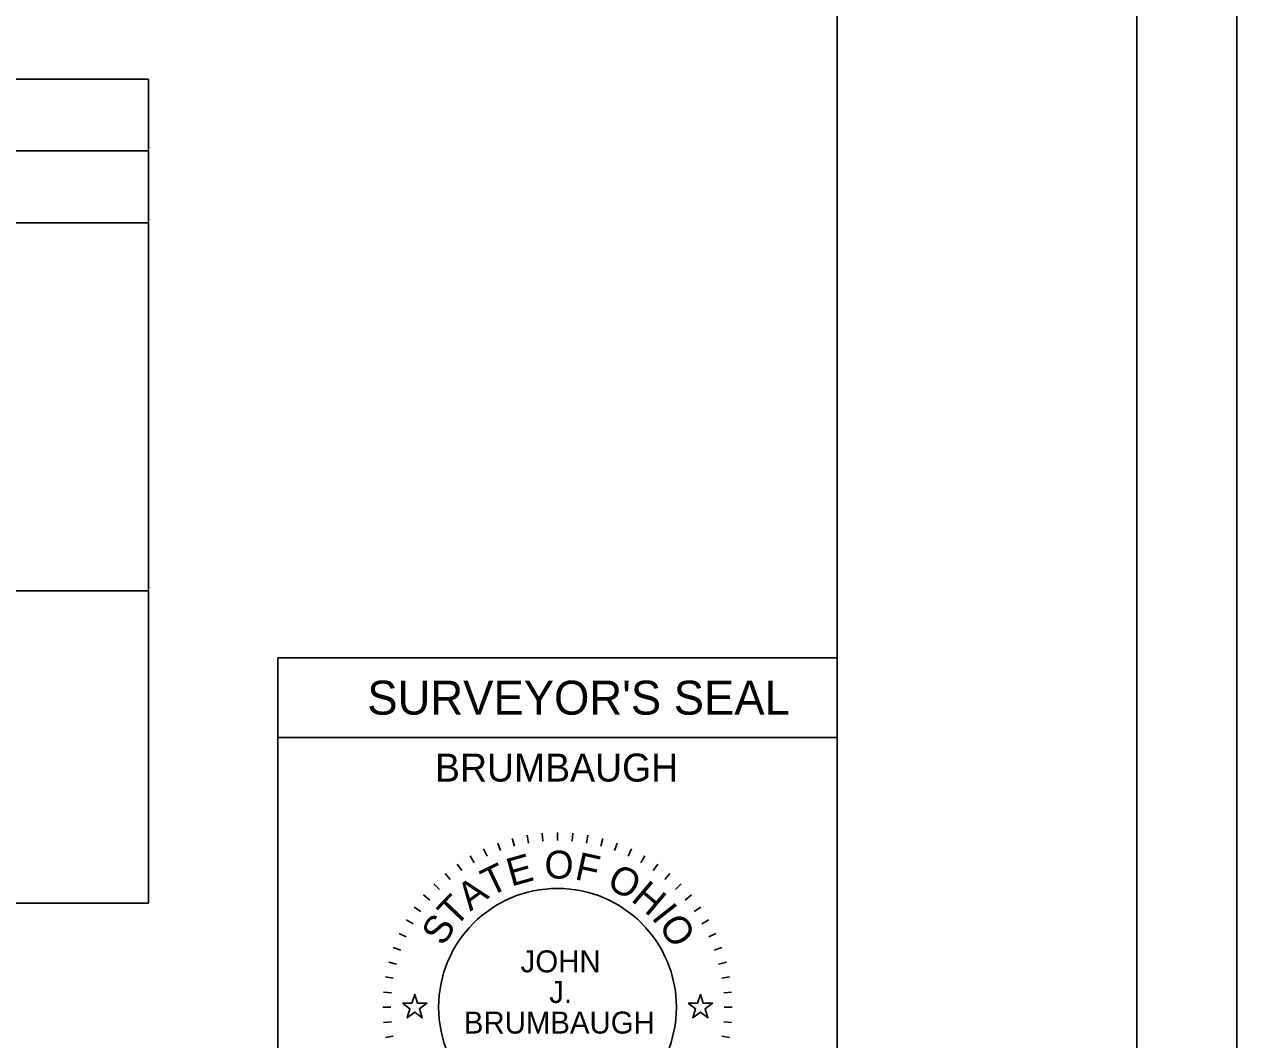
# Model space of a CAD drawing. Extents: x 0 to 34, y -5.4 to 22.
# Drawn here: x 27.93 to 34, y 5.09 to 10.17 of the extents above; entities that cross this region are included whole.
import ezdxf

# ---------------------------------------------------------------- set-up
doc = ezdxf.new("R2010")
doc.units = 0
for name, color, linetype in [('Default', 7, 'Continuous'), ('SH_Border', 7, 'Continuous'), ('SH_Cut_Line', 7, 'Continuous'), ('SH_Data', 7, 'Continuous')]:
    doc.layers.add(name, color=color, linetype=linetype)

msp = doc.modelspace()

# ---------------------------------------------------------------- linework, layer by layer
at = {"layer": 'Default'}
for points in [[(29.8236, 5.27), (29.8705, 5.27), (29.885, 5.3145), (29.8995, 5.27), (29.9464, 5.27), (29.9085, 5.2424), (29.923, 5.1978), (29.885, 5.2254), (29.847, 5.1978), (29.8615, 5.2424)], [(31.2536, 5.27), (31.3005, 5.27), (31.315, 5.3145), (31.3295, 5.27), (31.3764, 5.27), (31.3385, 5.2424), (31.353, 5.1978), (31.315, 5.2254), (31.277, 5.1978), (31.2915, 5.2424)]]:
    msp.add_lwpolyline(points, close=True, dxfattribs=at)
at = {"layer": 'SH_Border'}
msp.add_line((32, 0.5), (32, 21.5), dxfattribs=at)
msp.add_lwpolyline([(1.5, 21.5), (33.5, 21.5), (33.5, 0.5), (1.5, 0.5)], close=True, dxfattribs=at)
at = {"layer": 'SH_Cut_Line'}
msp.add_lwpolyline([(0, 0), (34, 0), (34, 22), (0, 22)], close=True, dxfattribs=at)
at = {"layer": 'SH_Data'}
for p, q in [((16.8678, 9.897), (28.5528, 9.897)), ((28.5528, 9.897), (28.5528, 5.7712)), ((16.8678, 9.537), (28.5528, 9.537)), ((16.8678, 9.177), (28.5528, 9.177)), ((16.8678, 7.3357), (28.5528, 7.3357)), ((32, 7), (29.2, 7)), ((29.2, 7), (29.2, 3.75)), ((32, 3.75), (32, 7)), ((32, 6.6), (29.2, 6.6)), ((30.3007, 6.0722), (30.3144, 6.0346)), ((30.3735, 6.0952), (30.3839, 6.0565)), ((30.4481, 6.1117), (30.455, 6.0723)), ((30.5237, 6.1217), (30.5272, 6.0818)), ((30.6, 6.125), (30.6, 6.085)), ((30.6763, 6.1217), (30.6728, 6.0818)), ((30.7519, 6.1117), (30.745, 6.0723)), ((30.8265, 6.0952), (30.8161, 6.0565)), ((30.8993, 6.0722), (30.8856, 6.0346)), ((30.2302, 6.043), (30.2471, 6.0068)), ((30.9698, 6.043), (30.9529, 6.0068)), ((30.0981, 5.9668), (30.1211, 5.934)), ((30.1625, 6.0078), (30.1825, 5.9731)), ((31.0375, 6.0078), (31.0175, 5.9731)), ((31.1019, 5.9668), (31.0789, 5.934)), ((30.0376, 5.9203), (30.0633, 5.8896)), ((31.1624, 5.9203), (31.1367, 5.8896)), ((29.9813, 5.8687), (30.0096, 5.8404)), ((31.2187, 5.8687), (31.1904, 5.8404)), ((16.8678, 5.7712), (28.5528, 5.7712)), ((29.9297, 5.8124), (29.9604, 5.7867)), ((31.2703, 5.8124), (31.2396, 5.7867)), ((29.8832, 5.7519), (29.916, 5.7289)), ((31.3168, 5.7519), (31.284, 5.7289)), ((29.8422, 5.6875), (29.8769, 5.6675)), ((31.3578, 5.6875), (31.3231, 5.6675)), ((29.807, 5.6198), (29.8432, 5.6029)), ((31.393, 5.6198), (31.3568, 5.6029)), ((29.7778, 5.5493), (29.8154, 5.5356)), ((31.4222, 5.5493), (31.3846, 5.5356)), ((29.7548, 5.4765), (29.7935, 5.4661)), ((31.4452, 5.4765), (31.4065, 5.4661)), ((29.7383, 5.4019), (29.7777, 5.395)), ((31.4617, 5.4019), (31.4223, 5.395)), ((29.7283, 5.3263), (29.7682, 5.3228)), ((31.4717, 5.3263), (31.4318, 5.3228)), ((29.725, 5.25), (29.765, 5.25)), ((31.475, 5.25), (31.435, 5.25)), ((29.7283, 5.1737), (29.7682, 5.1772)), ((31.4717, 5.1737), (31.4318, 5.1772)), ((29.7383, 5.0981), (29.7777, 5.105)), ((31.4617, 5.0981), (31.4223, 5.105))]:
    msp.add_line(p, q, dxfattribs=at)
msp.add_circle((30.6, 5.25), 0.595, dxfattribs=at)

# ---------------------------------------------------------------- texts
for s, height, p in [("SURVEYOR'S SEAL", 0.17, (29.6478, 6.715)), ('BRUMBAUGH', 0.14, (29.987, 6.38)), ('JOHN', 0.11, (30.4153, 5.4249)), ('J.', 0.11, (30.5587, 5.2716)), ('BRUMBAUGH', 0.11, (30.131, 5.1184))]:
    msp.add_text(s, height=height, dxfattribs=at).set_placement(p)
for s, rotation, p in [('E', 15.75706, (30.3684, 5.8538)), ('O', 359.78119, (30.5347, 5.8943)), ('F', 347.43619, (30.6811, 5.8917)), ('T', 25.71674, (30.2616, 5.8018)), ('O', 332.25863, (30.8398, 5.8515)), ('A', 36.47472, (30.1634, 5.7281)), ('H', 319.91363, (30.9632, 5.7861)), ('T', 46.4344, (30.0883, 5.6464)), ('I', 308.36695, (31.0665, 5.6983)), ('S', 57.19238, (30.0281, 5.5514)), ('O', 303.14906, (31.1021, 5.6589))]:
    msp.add_text(s, height=0.14, rotation=rotation, dxfattribs=at).set_placement(p)

doc.saveas('drawing.dxf')
